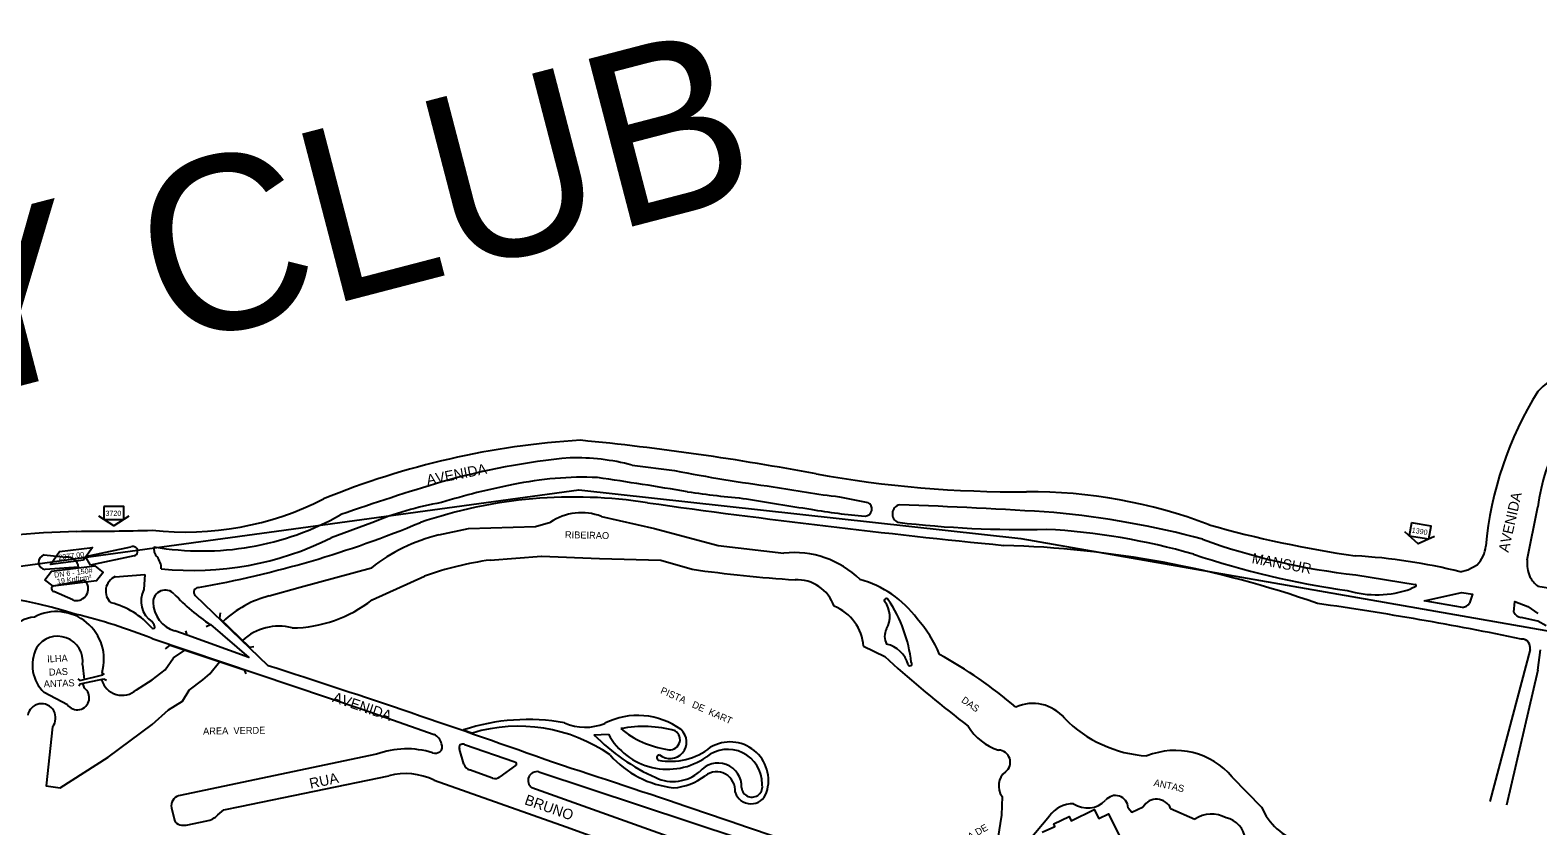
# Model space of a CAD drawing. Extents: x 325709 to 364434, y 7573432 to 7597073.
# Drawn here: x 332811 to 333681, y 7591100 to 7591559 of the extents above; entities that cross this region are included whole.
import ezdxf

# ---------------------------------------------------------------- set-up
doc = ezdxf.new("R2010")
doc.units = 0
for name, color, linetype in [('EDIFEXISTENT', 7, 'Continuous'), ('EDIFIDENTIF', 7, 'Continuous'), ('EDIFOBRAEXIS', 7, 'Continuous'), ('FORMATO', 7, 'Continuous'), ('LIMITE_BAIRROS_MUNICIPIOS', 7, 'Continuous'), ('LOGRADOURO', 7, 'Continuous'), ('LOGRADOURO_TEXTO', 7, 'Continuous'), ('NUM_REF', 7, 'Continuous'), ('SIMBOLO', 7, 'Continuous'), ('TEXTO', 7, 'Continuous'), ('TUBO_ACO_GN_6', 7, 'Continuous')]:
    doc.layers.add(name, color=color, linetype=linetype)

# ---------------------------------------------------------------- blocks, each defined once
blk = doc.blocks.new('NUM_REF')
at = {"layer": 'NUM_REF'}
blk.add_lwpolyline([(-4.3125, 0.9375), (0, 3.75), (4.3125, 0.9375)], dxfattribs=at)
blk.add_lwpolyline([(2.875, -1.875), (2.875, 1.875), (-2.875, 1.875), (-2.875, -1.875)], close=True, dxfattribs=at)

msp = doc.modelspace()

# ---------------------------------------------------------------- linework, layer by layer
at = {"layer": 'EDIFEXISTENT'}
for p, q in [((332839.78, 7591183.5), (332853.05, 7591186.9)), ((332853.05, 7591186.9), (332853.92, 7591187.7)), ((332838.5, 7591184.47), (332839.78, 7591183.5)), ((332839.21, 7591180.55), (332839.98, 7591181.67)), ((332839.98, 7591181.67), (332853.63, 7591184.47)), ((332853.63, 7591184.47), (332855.16, 7591183.81))]:
    msp.add_line(p, q, dxfattribs=at)
for points in [[(332920.74, 7591222.69), (332920.39, 7591219.64), (332937.64, 7591202.76), (332940.1, 7591203.25)], [(332912.62, 7591214.7), (332915.17, 7591215.8), (332937.3, 7591196.86), (332901.63, 7591209.69), (332900.84, 7591212.16)], [(332889.2, 7591201.9), (332891.8, 7591203.94), (332934.51, 7591189.71), (332935.64, 7591187.44)], [(333395.34, 7591095.94), (333402.65, 7591099.32), (333401.9, 7591100.79), (333410.77, 7591105.01), (333412, 7591102.66), (333425.3, 7591109.03), (333428.02, 7591103.98), (333433.53, 7591106.58), (333440.23, 7591092.99), (333431.36, 7591088.94), (333433.16, 7591085.33), (333427.7, 7591082.77), (333426.36, 7591085.58), (333422.22, 7591083.85), (333421.18, 7591086.32), (333417.11, 7591084.62), (333419.89, 7591078.99), (333410.27, 7591074.4), (333407.66, 7591080.14), (333405.94, 7591079.18), (333404.03, 7591083.51), (333401.79, 7591082.5)]]:
    msp.add_lwpolyline(points, dxfattribs=at)
at = {"layer": 'EDIFOBRAEXIS'}
for p, q in [((333158.53, 7591307.9), (333183.07, 7591304.69)), ((333278.34, 7591289.56), (333294.69, 7591286.39)), ((333008.27, 7591274.65), (332984.8, 7591265.88)), ((332819.05, 7591256.07), (332831.69, 7591254.81)), ((332871.02, 7591255.51), (332845.96, 7591250.16)), ((332839.04, 7591249.02), (332819.78, 7591247.61)), ((332824.51, 7591238.25), (332841.12, 7591241.36)), ((332860.18, 7591243.5), (332877.26, 7591244.82)), ((332877.26, 7591244.82), (332876.72, 7591236.04)), ((333576.37, 7591244.55), (333610.55, 7591238.93)), ((333610.89, 7591237.92), (333608.11, 7591236.53)), ((332835.7, 7591230.07), (332824.69, 7591234.92)), ((333637.91, 7591225.75), (333615.84, 7591229.59)), ((332901.63, 7591209.69), (332894.47, 7591212.22)), ((333681.39, 7591217.78), (333671.76, 7591219.84)), ((333686.13, 7591215.08), (333681.39, 7591217.78)), ((332914.85, 7591187.44), (332920.43, 7591194.41)), ((332841.34, 7591192.64), (332842.19, 7591184.12)), ((332852.55, 7591188.19), (332852.59, 7591186.79)), ((332832.57, 7591169.57), (332819.08, 7591176.66)), ((332841.34, 7591181.95), (332842.29, 7591179.24)), ((332872.36, 7591178.18), (332881.39, 7591183.91)), ((333408.08, 7591161.9), (333408.08, 7591161.9)), ((333061.14, 7591155.03), (333066.38, 7591153.24)), ((333136.53, 7591152.3), (333144.84, 7591152.57)), ((333061.47, 7591135.2), (333058.89, 7591143.88)), ((333061.79, 7591146.66), (333090.85, 7591136.59)), ((333091.22, 7591134.49), (333082.19, 7591127.95)), ((333078.01, 7591127.21), (333064.71, 7591131.93)), ((333104.68, 7591130.83), (333221.58, 7591092.24)), ((333194.9, 7591088), (333100.72, 7591121.67)), ((333469.42, 7591109.64), (333483.39, 7591103.48)), ((333387.27, 7591091.06), (333399.56, 7591105.38))]:
    msp.add_line(p, q, dxfattribs=at)
for points in [[(333046.95, 7591267.57), (333064.01, 7591271.32), (333064.01, 7591271.32), (333102.7, 7591272.4), (333111.36, 7591274.89)], [(333140.77, 7591278.3), (333171.51, 7591271.3), (333208.15, 7591261.49), (333246.15, 7591257.01)], [(332845.96, 7591250.16), (332842.97, 7591255.06), (332869.13, 7591260.68)], [(333076.62, 7591253.08), (333106.2, 7591255.31), (333106.2, 7591255.31), (333139.69, 7591254.02), (333139.69, 7591254.02), (333175.04, 7591253.12), (333193.17, 7591247.78)], [(332949.1, 7591232.41), (332966.89, 7591237.49), (333008.01, 7591248.68), (333008.01, 7591248.68)], [(333008.43, 7591230.2), (333008.43, 7591230.2), (333038.73, 7591243.79)], [(333615.84, 7591229.59), (333637.59, 7591234.42), (333643.58, 7591233.4), (333642.02, 7591228.19)], [(333667.58, 7591223.06), (333668.19, 7591229.12), (333675.62, 7591226.24), (333681.39, 7591222.22)], [(333292.13, 7591203.32), (333304.47, 7591197.37), (333309.35, 7591192.9)], [(332881.39, 7591183.91), (332888.94, 7591189.65), (332893.7, 7591196.69), (332893.7, 7591196.69), (332900.34, 7591201.12)], [(332881.39, 7591158.19), (332890.95, 7591166.6), (332898.92, 7591171.55), (332902.88, 7591177.92), (332910.72, 7591183.9), (332914.85, 7591187.44)], [(332823.95, 7591156.87), (332820.29, 7591122.73), (332828.38, 7591121.59), (332828.38, 7591121.59), (332856, 7591139.26), (332881.39, 7591158.19)], [(333504.93, 7591127.84), (333504.93, 7591127.84), (333521.92, 7591110.44)], [(333372.08, 7591116.61), (333371.81, 7591105.83), (333369.71, 7591092.55)], [(333444.89, 7591110.14), (333447.07, 7591107.49), (333453.53, 7591110.64)]]:
    msp.add_lwpolyline(points, dxfattribs=at)
for centre, radius, start, end in [((333160.18, 7590908.67), 405.16, 95.30659, 105.98382), ((333125.64, 7591181.99), 130.13, 75.36146, 91.28881), ((333130.12, 7591108.09), 192.79, 87.47221, 102.06812), ((332778.16, 7588857.19), 2469.95, 80.39191, 81.60842), ((333385.66, 7592363.18), 1077.71, 259.16484, 262.23473), ((333407.38, 7590090.64), 1259.69, 106.54711, 109.33146), ((333163.61, 7590915.04), 388.66, 100.94658, 107.23593), ((333299.06, 7592071.35), 786.4, 262.0588, 264.56148), ((333371.9, 7592037.02), 753.29, 259.91953, 262.86508), ((333082.09, 7591094.16), 195, 99.93372, 112.24518), ((333517.28, 7592974.3), 1711.04, 260.14848, 261.41181), ((333317.1, 7591589.55), 312.04, 259.78717, 265.56675), ((333292.76, 7591282.64), 4.21, 272.95434, 62.70336), ((333314.13, 7591279.75), 5.38, 103.65875, 245.47768), ((333200.26, 7588118.14), 3168.84, 86.35167, 87.96373), ((332910.37, 7591421.29), 162.97, 260.21332, 299.40246), ((333129.33, 7591248.38), 32.03, 69.07193, 124.12279), ((333384.64, 7591906.84), 636.15, 263.43368, 271.17087), ((333352.9, 7590761.29), 521.57, 75.00604, 84.60861), ((332905.01, 7591425.81), 178.73, 264.13354, 296.5146), ((333070.59, 7591169.23), 101.14, 103.52176, 128.22617), ((333376.07, 7590884.3), 387.12, 74.01508, 86.8061), ((333617.39, 7591622.19), 379.86, 250.05913, 263.80106), ((332820.22, 7591251.91), 4.32, 105.63368, 264.15485), ((332832.22, 7591247.93), 6.91, 9.08347, 94.3999), ((332870.34, 7591258.19), 2.77, 284.25664, 115.94508), ((332888.32, 7591259.21), 5.84, 165.36343, 227.66187), ((332875.19, 7591247.89), 11.56, 0.59802, 37.26853), ((333252.28, 7591203.59), 53.77, 45.31817, 96.54725), ((333639.33, 7591722.29), 491.48, 251.41409, 262.04911), ((333100.66, 7591073.12), 181.56, 97.60808, 109.94372), ((333301.63, 7592012.88), 772.75, 261.93133, 266.36069), ((332825.14, 7591236.62), 1.75, 111.09609, 255.04469), ((332837.79, 7591236.56), 6.82, 252.18477, 28.67876), ((332841.66, 7591239.23), 2.2, 16.13404, 104.35378), ((332863.64, 7591235.19), 9, 112.57366, 228.9987), ((333253.65, 7591219.02), 22.7, 18.96196, 92.69349), ((333273.91, 7591182.86), 61.14, 36.52653, 74.66366), ((333610.67, 7591238.41), 0.536, 293.96776, 102.91088), ((332889.2, 7591229.31), 14.18, 151.69996, 236.57857), ((332889.06, 7591228.74), 7.01, 42.67376, 180.89288), ((332975.06, 7591308.02), 109.96, 222.67091, 236.99891), ((332964.12, 7591173.8), 60.51, 104.37684, 133.54994), ((332961.7, 7591289.24), 75.3, 270.45361, 308.35753), ((333305.32, 7591229.72), 1.2, 22.52, 209.85126), ((333293.36, 7591220.41), 13.97, 329.42982, 38.59316), ((333240.47, 7591185.61), 79.61, 6.02662, 34.04993), ((333588.25, 7591291.01), 57.98, 253.05209, 290.03075), ((332815.46, 7591200.11), 20.2, 95.61734, 187.32896), ((332826.18, 7591195.87), 27.46, 343.76234, 117.54714), ((332846.72, 7591184.25), 45.51, 40.36472, 75.98751), ((332899.47, 7591228.9), 17.42, 180.89607, 253.34703), ((333265.53, 7591201.51), 26.66, 3.87942, 68.92641), ((333637.5, 7591231.14), 5.4, 274.39098, 326.9485), ((333672.66, 7591225.34), 5.57, 204.21957, 260.70754), ((332869.19, 7591208.26), 15.28, 26.37783, 37.05376), ((332881.89, 7591214.67), 1.07, 242.24412, 21.0822), ((332954.58, 7591184.37), 30.57, 75.37399, 133.10683), ((333313.25, 7591209.03), 8.95, 151.43528, 209.76815), ((333272.7, 7591173.32), 68.15, 21.77652, 42.37131), ((332826.93, 7591194.55), 14.53, 352.44784, 147.50919), ((333301.66, 7591188.09), 16.93, 16.18151, 76.96834), ((332834.36, 7591192.5), 22.01, 153.39648, 226.03573), ((333318.95, 7591193.13), 1.08, 197.15189, 50.7088), ((333204.95, 7590961), 271.34, 49.79331, 61.12408), ((333810.15, 7591755.7), 753.36, 228.33619, 232.59754), ((332838.22, 7591173.61), 6.95, 215.57238, 54.15706), ((332864.12, 7591187.31), 12.29, 195.36507, 312.08193), ((332817.62, 7591162), 8.15, 320.95376, 168.93597), ((333389.88, 7591146.44), 23.88, 40.34218, 114.15154), ((333098.32, 7591043.3), 117.75, 79.61762, 108.40536), ((333131.47, 7591186.2), 29.59, 246.2207, 292.39565), ((333161.82, 7591121.21), 42.2, 53.65863, 116.88573), ((333460.37, 7591212.97), 73.09, 224.32044, 266.36881), ((333093.01, 7591064.95), 92.22, 55.09639, 106.78392), ((333219.29, 7591233.3), 115.8, 224.38201, 245.98879), ((333178.98, 7591171.31), 38.95, 208.76989, 304.8553), ((333165.01, 7591089.95), 67.12, 74.05413, 101.18356), ((333186.95, 7591198.05), 54.84, 230.40184, 261.41654), ((333180.35, 7591148.13), 9.59, 230.7496, 47.48402), ((333180.32, 7591149.5), 5.89, 254.70113, 57.83885), ((333379.14, 7591172.86), 30.84, 210.43592, 252.80942), ((333061.04, 7591144.85), 2.36, 139.25384, 204.38518), ((333060.76, 7591144.3), 2.57, 66.47544, 125.81606), ((333180.79, 7591173.65), 36.73, 258.74001, 308.82006), ((333213.77, 7591124.09), 19.75, 359.15107, 129.38718), ((333215.05, 7591125.88), 22.21, 341.90395, 120.41216), ((333369.86, 7591136.42), 6.99, 307.19597, 88.59275), ((333471.97, 7591100.15), 43.05, 40.03843, 112.14744), ((333066.25, 7591136.7), 5.01, 197.39592, 252.13682), ((333090.74, 7591135.49), 1.11, 295.70977, 84.30901), ((333188.73, 7591178.82), 57.51, 221.67151, 263.63901), ((333174.45, 7591139.05), 1.65, 95.9203, 239.79215), ((333208.08, 7591122.23), 13.67, 357.90346, 140.88379), ((333079.35, 7591131.81), 4.79, 253.76041, 306.37225), ((333103.51, 7591125.9), 5.07, 76.6024, 236.62784), ((333182.22, 7591148.91), 23.63, 244.82048, 310.20103), ((333180.39, 7591154.5), 32.9, 273.42413, 307.98402), ((333207.27, 7591120.12), 10.74, 354.49022, 128.11362), ((333380.53, 7591122.69), 10.4, 128.28669, 215.75189), ((333227.08, 7591121.94), 9.56, 197.33804, 341.93639), ((333227.72, 7591122.25), 6, 184.97713, 14.9377), ((333437.53, 7591109.81), 7.36, 2.57005, 141.16356), ((333413.01, 7591096.16), 16.31, 88.70139, 145.55014), ((333421.43, 7591124.29), 14.31, 235.73909, 316.44316), ((333461.23, 7591106.2), 8.88, 22.78267, 150.04651), ((333555.88, 7591125.25), 37.05, 203.55052, 298.96773), ((333493.05, 7591089.68), 16.85, 60.23777, 124.98203), ((333498.31, 7591090.28), 14.37, 7.24845, 77.53099)]:
    msp.add_arc(centre, radius, start, end, dxfattribs=at)
at = {"layer": 'LOGRADOURO'}
for p, q in [((333675.26, 7591253.19), (333681.39, 7591283.77)), ((332948.43, 7591192.08), (332906.34, 7591232.62)), ((333676.87, 7591201.54), (333653.61, 7591113.76)), ((333681.39, 7591189.51), (333683.02, 7591201.26)), ((333681.39, 7591189.51), (333663.21, 7591111.7)), ((333010.94, 7591140.97), (332896.7, 7591117.01)), ((332892.65, 7591110.11), (332894.31, 7591102.92)), ((332904.78, 7591100.91), (332912.97, 7591102.62))]:
    msp.add_line(p, q, dxfattribs=at)
for points in [[(333636.6, 7591246.3), (333640.91, 7591247.44), (333646.27, 7591250.37)], [(333681.39, 7591238.02), (333868.02, 7591208.51), (333991.39, 7591189.46), (333999.35, 7591188.09)], [(332881.39, 7591207.86), (333003.34, 7591166.88), (333044.18, 7591152.34)], [(332919.4, 7591106.08), (332922.82, 7591108.83), (332932.37, 7591110.78), (333018.08, 7591128.56)], [(333044.32, 7591126.04), (333120.38, 7591099.06), (333187.51, 7591074.81)]]:
    msp.add_lwpolyline(points, dxfattribs=at)
for centre, radius, start, end in [((333741.04, 7591291.03), 84.16, 91.78101, 135.13234), ((333854.61, 7591242.27), 204.2, 148.02377, 174.69689), ((333156.76, 7590857.64), 465.44, 93.46257, 112.25828), ((332978.91, 7589785.38), 1544.12, 79.33056, 84.43503), ((333790.35, 7591270.24), 109.79, 150.61892, 172.92364), ((333381.37, 7591953.68), 661.23, 259.84485, 270.42528), ((333388.43, 7591003.45), 289.03, 69.07456, 90.42528), ((332900.68, 7591444.79), 175.57, 263.70245, 297.02553), ((333125.11, 7591013.63), 275.81, 81.16304, 108.78365), ((333872.94, 7596307.43), 5070.59, 262.00261, 264.34373), ((332799.68, 7591845.55), 617.91, 280.10282, 292.51606), ((333673.7, 7591922.27), 673.91, 254.32779, 261.66572), ((332864.27, 7590526.93), 743.19, 92.02207, 98.00798), ((332836.31, 7592919.8), 1650.14, 270.06023, 271.56659), ((333356.37, 7590664.66), 597.11, 70.64712, 88.38658), ((333558.94, 7590938.24), 317.69, 75.85061, 86.91895), ((333634.61, 7591262.35), 16.72, 314.21137, 355.82862), ((333694.31, 7591251.25), 19.15, 174.17344, 204.07263), ((333690.5, 7591250.33), 15.31, 206.72671, 233.49667), ((332752.7, 7590956.38), 278.6, 72.37421, 96.17284), ((332908.34, 7591234.63), 2.84, 158.60541, 225.0475), ((332908.28, 7591234.32), 2.91, 94.11074, 152.56883), ((332757.57, 7590893.99), 337.41, 68.47124, 76.3738), ((333279.9, 7589307.82), 1939.7, 78.34208, 81.86907), ((333672, 7591202.33), 5.18, 38.09325, 91.63417), ((333670.08, 7591202.27), 6.83, 353.8359, 28.52376), ((331333.85, 7586161.55), 5283.29, 70.31885, 72.20572), ((333041.3, 7591145.49), 7.43, 11.79612, 67.14955), ((333028.43, 7591093.9), 50.22, 72.66518, 110.3935), ((333044.79, 7591146.57), 4.94, 253.5855, 304.02048), ((333045.49, 7591145.32), 3.52, 306.06791, 28.74219), ((330534.5, 7583226.16), 8319.75, 70.760631, 71.943936), ((333027.74, 7591091.41), 38.39, 64.41669, 104.5881), ((332898.47, 7591111.34), 5.94, 107.26442, 191.92011), ((332898.61, 7591104.66), 4.64, 202.01259, 255.27228), ((332899.69, 7591114.75), 14.75, 261.20824, 290.18954), ((332911.77, 7591112.55), 10, 276.89997, 319.70167)]:
    msp.add_arc(centre, radius, start, end, dxfattribs=at)
at = {"layer": 'SIMBOLO'}
msp.add_lwpolyline([(332841.86, 7591252.97), (332822.79, 7591250.58), (332827.9, 7591258.02), (332846.97, 7591260.42)], close=True, dxfattribs=at)
msp.add_lwpolyline([(332819.47, 7591241.72), (332823.27, 7591246.61), (332848.32, 7591249.76), (332853.21, 7591245.96), (332849.41, 7591241.07), (332824.36, 7591237.93), (332819.47, 7591241.72)], dxfattribs=at)
at = {"layer": 'TUBO_ACO_GN_6'}
msp.add_lwpolyline([(332056.39, 7590927.25), (332098.18, 7590951.15), (332172.29, 7591021.22), (332302.53, 7591144.13), (332414.53, 7591196.65), (332573.34, 7591222.83), (332708.14, 7591236.35), (333127.77, 7591293.57), (333382.92, 7591265.62), (333749.6, 7591201.28), (334272.71, 7591124.55), (334289.54, 7591112.82), (334302.16, 7591074.68), (334343.48, 7590852.99), (334356.06, 7590808.95), (334377.62, 7590768.9), (334430.41, 7590707.68), (334461.91, 7590686.55)], dxfattribs=at)

# ---------------------------------------------------------------- block references
at = {"layer": 'FORMATO'}
for p, xscale, yscale, rotation in [((332859.34, 7591280.33), 1.999999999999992, 1.9999999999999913, 179.90572500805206), ((333613.48, 7591269.92), 1.9999999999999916, 1.9999999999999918, 170.6705775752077)]:
    msp.add_blockref('NUM_REF', p, dxfattribs=dict(at, xscale=xscale, yscale=yscale, rotation=rotation))

# ---------------------------------------------------------------- texts
for s, rotation, p in [('3720', 359.90572, (332854.47, 7591278.58)), ('1390', 350.67058, (333608.4, 7591268.98))]:
    msp.add_text(s, height=3, rotation=rotation).set_placement(p)
at = {"layer": 'EDIFIDENTIF'}
for s, rotation, p in [('RIBEIRAO', 358.66284, (333119.7, 7591265.77)), ('ILHA', 2.77249, (332820.93, 7591193.99)), ('DAS', 2.48504, (332821.93, 7591186.35)), ('ANTAS', 2.24033, (332818.95, 7591179.59)), ('PISTA   DE  KART', 336.00348, (333174.52, 7591176.35)), ('DAS', 324.92621, (333348.22, 7591171.36)), ('AREA  VERDE', 0.90587, (332910.88, 7591152.34)), ('ANTAS', 347.89687, (333459.36, 7591122.79)), ('CASA DE', 29.94302, (333344.06, 7591085.87))]:
    msp.add_text(s, height=4, rotation=rotation, dxfattribs=at).set_placement(p)
at = {"layer": 'LIMITE_BAIRROS_MUNICIPIOS'}
msp.add_text('LL BORTOLAN COUNTRY CLUB ', height=100, rotation=14.59155, dxfattribs=at).set_placement((331285.63, 7590957.98))
at = {"layer": 'LOGRADOURO_TEXTO'}
for s, rotation, p in [('AVENIDA', 10.94335, (333040.45, 7591296.29)), ('AVENIDA', 77.20108, (333664.4, 7591257.21)), ('MANSUR', 349.54943, (333515.94, 7591251.32)), ('AVENIDA', 341.33618, (332985.15, 7591171.4)), ('RUA', 12.14033, (332972.94, 7591121.05)), ('BRUNO', 340.73687, (333096, 7591112.27))]:
    msp.add_text(s, height=6, rotation=rotation, dxfattribs=at).set_placement(p)
at = {"layer": 'TEXTO'}
for s, p in [('2377,00', (332827.55, 7591253.07)), ('DN 6 - 150#', (332825.07, 7591242.93)), ('19 Kgf/cm²', (332826.7, 7591239.3))]:
    msp.add_text(s, height=3, rotation=7.16234, dxfattribs=at).set_placement(p)

doc.saveas('drawing.dxf')
